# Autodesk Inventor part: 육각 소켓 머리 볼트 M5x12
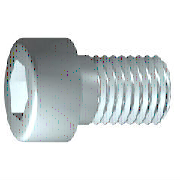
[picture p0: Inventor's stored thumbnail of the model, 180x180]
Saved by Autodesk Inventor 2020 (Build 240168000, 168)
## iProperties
Created: 2012-02
Part Number: 육각 소켓 머리 볼트 M5x12
Material: 강철, 연강
Description: 6각 소켓 머리 캡 나사
Document SubType Name: Modeling
Standard: ISO 4762
Designer: mdu-01
Standard Revision: Fourth edition 2004-03-01
Standards Organization: ISO
Language: ko-KR
Size Designation: M5 x 12
Categories: <MemberInstance><Categories><Category DisplayName="조임쇠" InternalName="e4da775c-781d-43d5-af7c-5136215cf5a6" Mnemonic="FSTN"><Category DisplayName="볼트" InternalN
Density: 7.75 g/cm^3
Appearance: 강철
IsCustomPart: 1
Author: mdu-01
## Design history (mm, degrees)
sketch "스케치1"
  geometry: L1 (-1.167, 0)-(12, 0); L2 (12, 0)-(12, 2.5); L3 (12, 2.5)-(2, 2.5); L4 (2, 2.5)-(1.509, 2.5); L5 (1.509, 2.5)-(0, 2.5); L6 (0, 2.5)-(0, 4.25); L7 (0, 4.25)-(-5, 4.25); L8 (-5, 4.25)-(-5, 2.309); L9 (-5, 2.309)-(-2.5, 2.309); L10 (-2.5, 2.309)-(-1.167, 0); L11 (-8.4, 0)-(15.4, 0) reference; L12 (0, -0.85)-(0, 5.1) reference; L13 (2, 2.5)-(0, 2.5)
  constraints: 22 end point, 6 parallel, 2 collinear, 2 perpendicular, 1 horizontal, 1 point on line
  dimensions: "d1" = 10 distance from line of L3.end L2 (= GEL); "d2" = 0.49086 distance of L4.end L3.end (computed from GAL); "d3" = 5 distance between parallel lines of L8 L6 (= KOH); "d4" = 2.5 distance of L8.end L9.end (= INTI); "d5" = 60 deg angle of L10 L1; "d6" = 5 diameter of L3 L1 (= GD); "d7" = 5 diameter of L5 L1 (= BDM); "d8" = 4.6188 diameter of L9 L1 (= 1.1547 x SW); "d9" = 8.5 diameter of L7 L1 (= KOD); "d26" = 12 distance between parallel lines of L12 L2 (= NLG)
revolve "본체" sketch "스케치1" stored, may be unused: angle "d10" = 90 deg
sketch "스케치2"
  geometry: L1 (0, -5.95)-(0, 5.95) reference; L2 (-5.95, 0)-(5.95, 0) reference; L3 (2.309, 0)-(1.155, -2); L4 (1.155, -2)-(-1.155, -2); L5 (-1.155, -2)-(-2.309, 0); L6 (-2.309, 0)-(-1.155, 2); L7 (-1.155, 2)-(1.155, 2); L8 (1.155, 2)-(2.309, 0); 2 further points
  constraints: 12 end point, 1 coincident, 1 horizontal alignment, 1 point on line, 12 other
extrude "슬롯" join sketch "스케치2" stored distance "d11" = 10; taper "d12" = 0 deg
workplane "Work Plane1"
fillet "Fillet2" dims "d30" = 0.1 (= R)
body "Solid1"
fillet "모깎기1" dims "d17" = 0.5 (= RR)
feature "스레드" dims "d13" = 10 (= GEL), "d14" = 0
chamfer "모따기1" distance "d15" = 0.49076 (= -0.5 x SPD + 0.5 x GD); stored, may be unused: second distance "d16" = 0.49076 (= GUL), angle "d27" = 45 deg
other parameters: "GD" = 5 [user parameter; used in 2 equation terms], "NLG" = 12 [user parameter; used in 1 equation term], "GEL" = 10 [user parameter; used in 2 equation terms], "KOD" = 8.5 [user parameter; used in 1 equation term], "KOH" = 5 [user parameter; used in 1 equation term], "INTI" = 2.5 [user parameter; used in 1 equation term], "GAL" = 0.49076 (= 0.61345 x PTC) [user parameter; used in 1 equation term], "GUL" = 0.49076 (= 0.61345 x PTC) [user parameter; used in 1 equation term], "BDM" = 5 (= NND) [user parameter; used in 1 equation term], "SW" = 4 [user parameter; used in 2 equation terms], "RR" = 0.5 [user parameter; used in 1 equation term], "SPD" = 4.01848 (= NND - 1.2269 x PTC) [user parameter; used in 1 equation term], "d19" = 0, "d28" = 0, "d29" = 0, "R" = 0.1 [user parameter; used in 1 equation term], "TOA" = 30 deg [user parameter], "GD1" = 4.01848 (= THREADDIA - 1.2269 x PTC) [user parameter], "THREADDIA" = 5 [user parameter; used in 1 equation term], "FAWI" = 45 deg [user parameter], "TPU" = 12.5 (computed from PTC) [user parameter], "PTC" = 0.8 [user parameter; used in 5 equation terms], "NND" = 5 [user parameter; used in 2 equation terms], "E0" = 4.62 (= 1.155 x SW) [user parameter]
